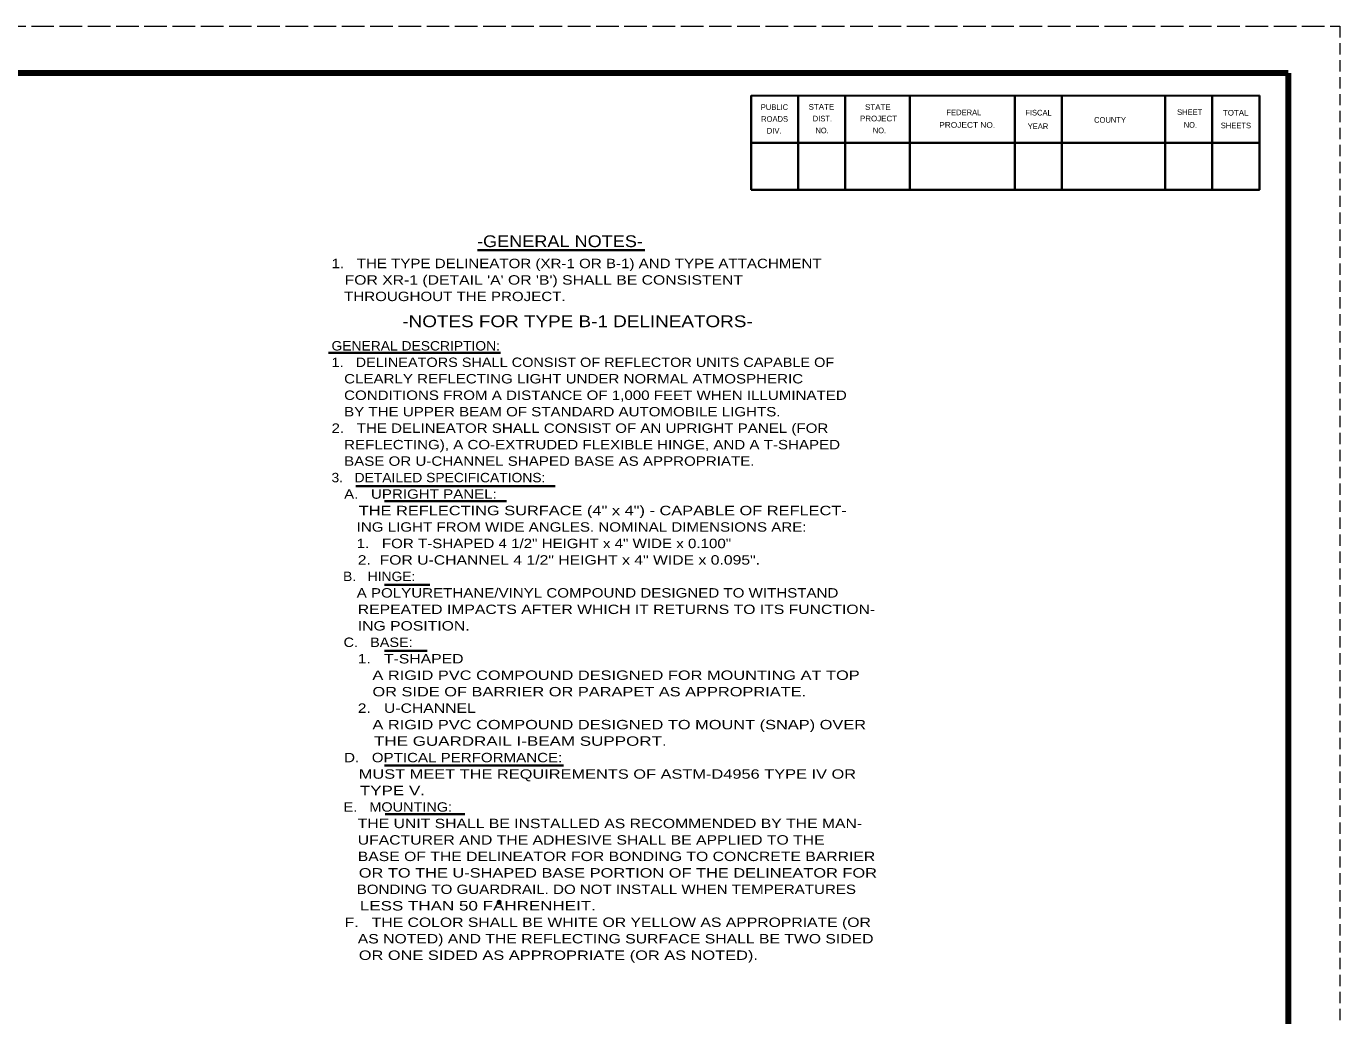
# Model space of a CAD drawing. Extents: x -60 to 620, y -42 to 398.
# Drawn here: x 340.7 to 619.8, y 188 to 398.3 of the extents above; entities that cross this region are included whole.
import ezdxf
from ezdxf.enums import TextEntityAlignment as Align

# ---------------------------------------------------------------- set-up
doc = ezdxf.new("R2010")
doc.units = 0
doc.header["$LTSCALE"] = 0.8
doc.linetypes.add('LONG_DASHED', pattern=[7.5, 6, -1.5])
doc.linetypes.add('MEDIUM_DASHED', pattern=[4.5, 3, -1.5])
doc.layers.add('1', color=7, linetype='Continuous', lineweight=35)
doc.layers.add('61', color=7, linetype='Continuous', lineweight=35)

msp = doc.modelspace()

# ---------------------------------------------------------------- linework, layer by layer
at = {"layer": '1', "linetype": 'MEDIUM_DASHED', "lineweight": 13}
msp.add_line((619.8045, 398.2688), (619.7845, -41.7512), dxfattribs=at)
at = {"layer": '1'}
for p, q in [((436.5861, 350.678), (472.1223, 350.678)), ((404.941, 328.8676), (441.4651, 328.8676)), ((410.7601, 300.5611), (453.0799, 300.5611)), ((416.8143, 297.3343), (442.7184, 297.3343)), ((416.8143, 279.6024), (426.4231, 279.6024)), ((416.8057, 265.5647), (425.8743, 265.5647)), ((416.8057, 241.1832), (454.8581, 241.1832)), ((416.9836, 230.8396), (433.876, 230.8396))]:
    msp.add_line(p, q, dxfattribs=at)
msp.add_circle((441.1875, 212.0696), 0.3487, dxfattribs=at)
at = {"layer": '61', "linetype": 'LONG_DASHED', "lineweight": 13}
msp.add_line((-60.2155, 398.2688), (619.8045, 398.2688), dxfattribs=at)
at = {"layer": '61', "lineweight": 158}
msp.add_line((608.8245, 388.2688), (608.8445, -31.7712), dxfattribs=at)
at = {"layer": '61'}
for p, q in [((504.7445, 383.5087), (504.7445, 363.5087)), ((514.7445, 383.5087), (514.7445, 363.5087)), ((528.4245, 383.5087), (528.4245, 363.5087)), ((550.7445, 383.5087), (550.7445, 363.5087)), ((560.7445, 383.5087), (560.7445, 363.5087)), ((582.7245, 383.5288), (582.7245, 363.5288)), ((592.7245, 383.5288), (592.7245, 363.5288)), ((602.7445, 373.4887), (494.7245, 373.5087))]:
    msp.add_line(p, q, dxfattribs=at)
at = {"layer": '61', "lineweight": 158}
msp.add_lwpolyline([(608.8245, 388.2688), (-30.2155, 388.2688), (-30.2155, -31.7512)], dxfattribs=at)
at = {"layer": '61'}
for points in [[(602.7245, 383.5288), (494.7445, 383.5087), (494.7445, 363.5087)], [(602.7245, 383.5288), (602.7245, 363.5288), (494.7445, 363.5087)]]:
    msp.add_lwpolyline(points, dxfattribs=at)

# ---------------------------------------------------------------- texts
at = {"layer": '1'}
for s, width, p in [('-GENERAL NOTES-', 1.15, (454.1112, 351.3413)), ('-NOTES FOR TYPE B-1 DELINEATORS-', 1.2, (457.8363, 334.3248))]:
    msp.add_text(s, height=2.5, dxfattribs=dict(at, width=width)).set_placement(p, align=Align.CENTER)
for s, width, p in [('1.   THE TYPE DELINEATOR (XR-1 OR B-1) AND TYPE ATTACHMENT', 1.2, (405.5646, 346.863)), ("   FOR XR-1 (DETAIL 'A' OR 'B') SHALL BE CONSISTENT", 1.25, (405.5646, 343.363)), ('   THROUGHOUT THE PROJECT.', 1.2, (405.5646, 339.863)), ('GENERAL DESCRIPTION:', 1.1, (405.5646, 329.363)), ('1.   DELINEATORS SHALL CONSIST OF REFLECTOR UNITS CAPABLE OF', 1.15, (405.5646, 325.863)), ('   CLEARLY REFLECTING LIGHT UNDER NORMAL ATMOSPHERIC', 1.2, (405.5646, 322.363)), ('   CONDITIONS FROM A DISTANCE OF 1,000 FEET WHEN ILLUMINATED', 1.2, (405.5646, 318.863)), ('   BY THE UPPER BEAM OF STANDARD AUTOMOBILE LIGHTS.', 1.2, (405.5646, 315.363)), ('2.   THE DELINEATOR SHALL CONSIST OF AN UPRIGHT PANEL (FOR', 1.2, (405.5646, 311.863)), ('   REFLECTING), A CO-EXTRUDED FLEXIBLE HINGE, AND A T-SHAPED', 1.2, (405.5646, 308.363)), ('   BASE OR U-CHANNEL SHAPED BASE AS APPROPRIATE.', 1.2, (405.5646, 304.863)), ('3.   DETAILED SPECIFICATIONS:', 1.1, (405.5646, 301.363)), ('   A.   UPRIGHT PANEL:', 1.2, (405.5646, 297.863)), ('      THE REFLECTING SURFACE (4" x 4") - CAPABLE OF REFLECT-', 1.3, (405.5646, 294.363)), ('      ING LIGHT FROM WIDE ANGLES. NOMINAL DIMENSIONS ARE:', 1.2, (405.5646, 290.863)), ('      1.   FOR T-SHAPED 4 1/2" HEIGHT x 4" WIDE x 0.100"', 1.2, (405.5646, 287.363)), ('      2.  FOR U-CHANNEL 4 1/2" HEIGHT x 4" WIDE x 0.095".', 1.25, (405.5646, 283.863)), ('   B.   HINGE:', 1.1, (405.5646, 280.363)), ('      A POLYURETHANE/VINYL COMPOUND DESIGNED TO WITHSTAND', 1.2, (405.5646, 276.863)), ('      REPEATED IMPACTS AFTER WHICH IT RETURNS TO ITS FUNCTION-', 1.25, (405.5646, 273.363)), ('      ING POSITION.', 1.25, (405.5646, 269.863)), ('   C.   BASE:', 1.15, (405.5646, 266.363)), ('      1.   T-SHAPED', 1.25, (405.5646, 262.863)), ('         A RIGID PVC COMPOUND DESIGNED FOR MOUNTING AT TOP', 1.3, (405.5646, 259.363)), ('         OR SIDE OF BARRIER OR PARAPET AS APPROPRIATE.', 1.3, (405.5646, 255.863)), ('      2.   U-CHANNEL', 1.25, (405.5646, 252.363)), ('         A RIGID PVC COMPOUND DESIGNED TO MOUNT (SNAP) OVER', 1.3, (405.5646, 248.863)), ('         THE GUARDRAIL I-BEAM SUPPORT.', 1.35, (405.5646, 245.363)), ('   D.   OPTICAL PERFORMANCE:', 1.2, (405.5646, 241.863)), ('      MUST MEET THE REQUIREMENTS OF ASTM-D4956 TYPE IV OR', 1.3, (405.5646, 238.363)), ('      TYPE V.', 1.35, (405.5646, 234.863)), ('   E.   MOUNTING:', 1.15, (405.5646, 231.363)), ('      THE UNIT SHALL BE INSTALLED AS RECOMMENDED BY THE MAN-', 1.25, (405.5646, 227.863)), ('      UFACTURER AND THE ADHESIVE SHALL BE APPLIED TO THE', 1.25, (405.5646, 224.363)), ('      BASE OF THE DELINEATOR FOR BONDING TO CONCRETE BARRIER', 1.25, (405.5646, 220.863)), ('      OR TO THE U-SHAPED BASE PORTION OF THE DELINEATOR FOR', 1.3, (405.5646, 217.363)), ('      BONDING TO GUARDRAIL. DO NOT INSTALL WHEN TEMPERATURES', 1.2, (405.5646, 213.863)), ('      LESS THAN 50 FAHRENHEIT.', 1.35, (405.5646, 210.363)), ('   F.   THE COLOR SHALL BE WHITE OR YELLOW AS APPROPRIATE (OR', 1.25, (405.5646, 206.863)), ('      AS NOTED) AND THE REFLECTING SURFACE SHALL BE TWO SIDED', 1.25, (405.5646, 203.363)), ('      OR ONE SIDED AS APPROPRIATE (OR AS NOTED).', 1.3, (405.5646, 199.863))]:
    msp.add_text(s, height=2, dxfattribs=dict(at, width=width)).set_placement(p)
at = {"layer": '61'}
for s, rotation, p in [('PUBLIC', 0.033, (496.7845, 380.4887)), ('FEDERAL', 0.007, (536.2445, 379.3687)), ('FISCAL', 359.942, (552.9845, 379.3087)), ('SHEET', 0.059, (585.2445, 379.4287)), ('ROADS', 0.124, (496.8645, 377.9688)), ('DIST.', 0.056, (507.8245, 378.0487)), ('YEAR', 0.105, (553.5045, 376.4087)), ('COUNTY', 0.069, (567.6045, 377.7688)), ('SHEETS', 359.959, (594.5245, 376.5888)), ('DIV.', 359.932, (498.0645, 375.4688))]:
    msp.add_text(s, height=1.201, rotation=rotation, dxfattribs=at).set_placement(p)
for s, rotation, width, p in [('STATE', 0.059, 1.05, (506.9445, 380.5487)), ('STATE', 0.059, 1.05, (518.9445, 380.4887)), ('TOTAL', 359.926, 1.05, (594.9845, 379.2887)), ('PROJECT', 359.908, 1.05, (517.8645, 378.0687)), ('PROJECT NO.', 359.922, 1.1, (534.7045, 376.7088)), ('NO.', 359.852, 0.95, (586.6645, 376.7088)), ('NO.', 359.852, 0.95, (508.4045, 375.5288)), ('NO.', 0.225, 0.95, (520.6045, 375.5288))]:
    msp.add_text(s, height=1.201, rotation=rotation, dxfattribs=dict(at, width=width)).set_placement(p)

doc.saveas('drawing.dxf')
